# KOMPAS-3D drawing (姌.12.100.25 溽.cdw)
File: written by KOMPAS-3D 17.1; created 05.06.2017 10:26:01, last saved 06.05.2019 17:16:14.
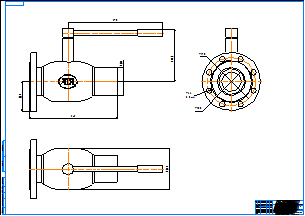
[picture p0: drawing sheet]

Sheet 1: A0, landscape

Title block, sheet 1: name: КШ.12.100.25 фс; material: Внимание! Данный продукт является объектом авторского права ООО «Торговый Дом АДЛ». / Запрещается изменение, копирование, распространение / (в том числе путем копирования на другие сайты и ресурсы в Интернете) / или любое иное использование информации и объектов без предварительного / согласия правообладателя (ООО «Торговый Дом АДЛ»).; sheets: 1; organisation: ООО "Торговый дом АДЛ"; sheet format: A0; stored path: C:\Users\kka\KOMPAS_Work\Модели кранов для исследований\Все краники\Редуцированный резьба-сварка ШК БИВАЛ\КШ.02.015.40 рс.cdw

Views: Вид 1, Проекционный вид 4, Проекционный вид 5
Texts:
  Klimkovich
  ADL
Dimensions and other numbers on the sheet: 370; 108; 345; 205,1; 190; 115; 100; 22; 8 Отв.; 159; 1:1; 1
